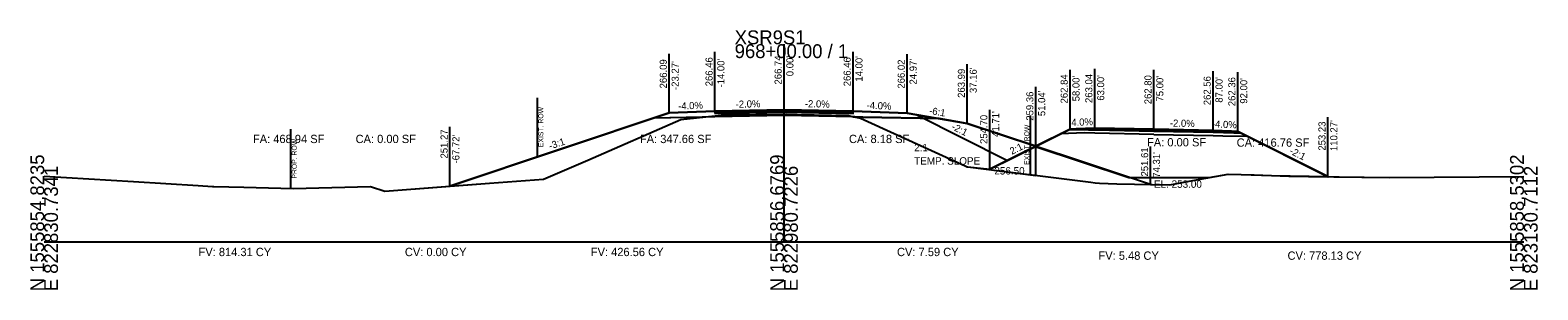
# Model space of a CAD drawing. Extents: x -26 to 823017, y -16 to 1558356.
# Drawn here: x 997.2 to 1302.8, y 7990.3 to 8042.8 of the extents above; entities that cross this region are included whole.
import ezdxf

# ---------------------------------------------------------------- set-up
doc = ezdxf.new("R2010")
doc.units = 0
for name, color, linetype in [('1', 7, 'Continuous'), ('ASPHALT_19MM1', 7, 'Continuous'), ('ASPHALT_9_5MM1', 7, 'Continuous'), ('CONST_DCH', 7, 'Continuous'), ('CONST_LV3', 7, 'Continuous'), ('Draft_XS_Grid', 7, 'Continuous'), ('DTM_CORRIDOR', 7, 'Continuous'), ('DTM_P_FINISHED_GRADE2', 7, 'Continuous'), ('DTM_X_GROUND', 7, 'Continuous'), ('SLOPE_STAKES_FILL', 7, 'Continuous'), ('X_PROFILES_1', 7, 'Continuous'), ('X_TRANS_EOP', 7, 'Continuous'), ('XS_CELL', 7, 'Continuous'), ('XS_M_SHAPES_EARTHWORK', 7, 'Continuous'), ('XS_P_DR_GRAVEL', 7, 'Continuous'), ('XS_P_GROUND', 7, 'Continuous'), ('XS_P_NULL_POINT', 7, 'Continuous'), ('XS_P_ROW', 7, 'Continuous'), ('XS_P_SHOULDER', 7, 'Continuous'), ('XS_P_SUBGRADE_GRANULAR', 7, 'Continuous'), ('XS_P_SUBGRADE_UNDERCUT', 7, 'Continuous'), ('XS_P_TX_CLEARZONE', 7, 'Continuous'), ('XS_P_TX_FS_BS', 7, 'Continuous'), ('XS_SHEET_EW_TX_AREA', 7, 'Continuous'), ('XS_SHEET_EW_TX_VOLUME', 7, 'Continuous'), ('XS_X_ROW', 7, 'Continuous')]:
    doc.layers.add(name, color=color, linetype=linetype)

msp = doc.modelspace()

# ---------------------------------------------------------------- linework, layer by layer
at = {"layer": '1'}
msp.add_lwpolyline([(1136, 8026.17), (1136, 8026.17), (1136, 8026.17), (1150, 8026.45), (1164, 8026.17), (1164, 8026.17), (1164, 8026.17), (1164, 8026.33), (1164, 8026.33), (1150, 8026.61), (1136, 8026.33), (1136, 8026.33), (1136, 8026.17)], dxfattribs=at)
at = {"layer": 'ASPHALT_19MM1'}
for points in [[(1136, 8025.96), (1136, 8025.96), (1136, 8025.96), (1150, 8026.24), (1164, 8025.96), (1164, 8025.96), (1164, 8025.96), (1164, 8026.17), (1164, 8026.17), (1150, 8026.45), (1136, 8026.17), (1136, 8026.17), (1136, 8025.96)], [(1213, 8022.67), (1225, 8022.43), (1237, 8022.19), (1237, 8022.4), (1225, 8022.64), (1213, 8022.88), (1213, 8022.67)]]:
    msp.add_lwpolyline(points, dxfattribs=at)
at = {"layer": 'ASPHALT_9_5MM1'}
msp.add_lwpolyline([(1136, 8026.33), (1136, 8026.33), (1136, 8026.33), (1150, 8026.61), (1164, 8026.33), (1164, 8026.33), (1164, 8026.33), (1164, 8026.46), (1164, 8026.46), (1150, 8026.74), (1136, 8026.46), (1136, 8026.46), (1136, 8026.33)], dxfattribs=at)
at = {"layer": 'CONST_LV3'}
for points in [[(1150, 8026.74), (1164, 8026.46)], [(1174.97, 8026.02), (1174.97, 8026.02), (1164, 8026.46)], [(1187.16, 8023.99), (1187.16, 8023.99), (1181.43, 8024.94)], [(1191.71, 8014.7), (1196.39, 8017.04), (1208, 8022.84), (1209.25, 8022.89), (1213, 8023.04)], [(1201.04, 8019.36), (1201.04, 8019.36), (1201.34, 8019.52), (1208, 8022.84), (1209.25, 8022.89), (1213, 8023.04), (1215.99, 8022.98), (1225, 8022.8), (1234.01, 8022.34), (1237, 8022.19), (1240.75, 8022.32), (1242, 8022.36), (1255.46, 8015.63), (1260.27, 8013.23), (1261.5, 8013.18), (1272.75, 8013.02), (1300, 8013.26)], [(1242, 8022.36), (1260.32, 8013.2)], [(1000, 8013.3), (1018.08, 8012.21), (1031.23, 8011.41), (1034.12, 8011.23), (1034.39, 8011.22), (1040.49, 8011.05), (1050.5, 8010.79), (1066.18, 8011.18), (1069.08, 8010.24), (1082.28, 8011.27), (1082.28, 8011.27)]]:
    msp.add_lwpolyline(points, dxfattribs=at)
at = {"layer": 'DTM_P_FINISHED_GRADE2'}
msp.add_lwpolyline([(1082.28, 8011.27), (1082.28, 8011.27), (1126.73, 8026.09), (1136, 8026.46), (1150, 8026.74), (1164, 8026.46), (1174.97, 8026.02), (1187.16, 8023.99), (1201.04, 8019.36)], dxfattribs=at)
at = {"layer": 'DTM_X_GROUND'}
for points in [[(1000, 8013.3), (1018.08, 8012.21), (1031.23, 8011.41), (1034.12, 8011.23), (1034.39, 8011.22), (1040.49, 8011.05), (1050.5, 8010.79), (1066.18, 8011.18), (1069.08, 8010.24), (1082.28, 8011.27), (1082.28, 8011.27), (1082.28, 8011.27), (1126.73, 8026.09), (1126.73, 8026.09), (1136, 8026.46), (1136, 8026.46), (1150, 8026.74), (1164, 8026.46), (1164, 8026.46), (1174.97, 8026.02), (1174.97, 8026.02), (1187.16, 8023.99), (1187.16, 8023.99), (1201.04, 8019.36), (1201.04, 8019.36), (1201.04, 8019.36), (1201.34, 8019.52), (1208, 8022.84), (1209.25, 8022.89), (1213, 8023.04), (1215.99, 8022.98), (1225, 8022.8), (1234.01, 8022.34), (1237, 8022.19), (1240.75, 8022.32), (1242, 8022.36), (1255.46, 8015.63), (1260.27, 8013.23), (1261.5, 8013.18), (1272.75, 8013.02), (1300, 8013.26)], [(1000, 8013.3), (1018.08, 8012.21), (1031.23, 8011.41), (1034.12, 8011.23), (1034.39, 8011.22), (1040.49, 8011.05), (1050.5, 8010.79), (1066.18, 8011.18), (1069.08, 8010.24), (1090.32, 8011.9), (1101.23, 8012.68), (1110.24, 8016.53), (1129.11, 8024.79), (1137.35, 8025.65), (1137.69, 8025.69), (1137.92, 8025.69), (1150.57, 8025.82), (1152.65, 8025.78), (1163.07, 8025.58), (1163.82, 8025.41), (1165.51, 8025.03), (1186.7, 8015.39), (1187.14, 8015.2), (1187.24, 8015.19), (1212.19, 8012.07), (1213.08, 8011.97), (1213.97, 8011.88), (1217.45, 8011.73), (1228.25, 8011.53), (1232.89, 8012.43), (1240.07, 8013.71), (1245.35, 8013.54), (1252.34, 8013.32), (1272.75, 8013.02), (1300, 8013.26)], [(1000, 8013.3), (1018.08, 8012.21), (1031.23, 8011.41), (1034.12, 8011.23), (1034.39, 8011.22), (1040.49, 8011.05), (1050.5, 8010.79), (1066.18, 8011.18), (1069.08, 8010.24), (1090.32, 8011.9), (1101.23, 8012.68), (1110.24, 8016.53), (1129.11, 8024.79), (1137.35, 8025.65), (1137.69, 8025.69), (1137.92, 8025.69), (1150.57, 8025.82), (1152.65, 8025.78), (1163.07, 8025.58), (1163.82, 8025.41), (1165.51, 8025.03), (1186.7, 8015.39), (1187.14, 8015.2), (1187.24, 8015.19), (1187.25, 8015.19), (1191.71, 8014.7), (1196.39, 8017.04), (1208, 8022.84), (1209.25, 8022.89), (1213, 8023.04), (1215.99, 8022.98), (1225, 8022.8), (1234.01, 8022.34), (1237, 8022.19), (1240.75, 8022.32), (1242, 8022.36), (1255.46, 8015.63), (1260.27, 8013.23), (1261.5, 8013.18), (1272.75, 8013.02), (1300, 8013.26)]]:
    msp.add_lwpolyline(points, dxfattribs=at)
at = {"layer": 'X_TRANS_EOP'}
msp.add_lwpolyline([(1213, 8022.88), (1225, 8022.64), (1237, 8022.4), (1237, 8022.56), (1225, 8022.8), (1213, 8023.04), (1213, 8022.88)], dxfattribs=at)
at = {"layer": 'XS_CELL'}
for p, q in [((1150, 8000), (1150, 8040)), ((1000, 8000), (1150, 8000)), ((1150, 8000), (1300, 8000))]:
    msp.add_line(p, q, dxfattribs=at)
at = {"layer": 'XS_M_SHAPES_EARTHWORK'}
for points in [[(1082.28, 8011.27), (1090.32, 8011.9), (1101.23, 8012.68), (1110.24, 8016.53), (1129.11, 8024.79), (1133.43, 8025.24), (1123.59, 8025.05)], [(1133.43, 8025.24), (1137.35, 8025.65), (1137.69, 8025.69), (1137.92, 8025.69), (1150.57, 8025.82), (1152.65, 8025.78), (1163.07, 8025.58), (1163.82, 8025.41), (1164.38, 8025.29), (1164, 8025.29), (1150, 8025.57), (1136, 8025.29), (1134, 8025.25)], [(1164.38, 8025.29), (1165.51, 8025.03), (1186.7, 8015.39), (1187.14, 8015.2), (1187.24, 8015.19), (1201.04, 8013.46), (1201.04, 8019.36), (1187.16, 8023.99), (1181.43, 8024.94), (1166, 8025.25)]]:
    msp.add_lwpolyline(points, close=True, dxfattribs=at)
at = {"layer": 'XS_P_DR_GRAVEL'}
for points in [[(1209.25, 8022.89), (1208, 8022.84), (1207.89, 8022.79), (1207.86, 8022.77), (1211.72, 8022.69), (1213, 8022.67), (1213, 8022.76), (1213, 8023.04), (1209.25, 8022.89)], [(1240.75, 8022.41), (1237, 8022.56), (1237, 8022.28), (1237, 8022.19), (1241.18, 8022.1), (1242.57, 8022.08), (1242.43, 8022.15), (1242, 8022.36), (1240.75, 8022.41)]]:
    msp.add_lwpolyline(points, dxfattribs=at)
at = {"layer": 'XS_P_GROUND'}
msp.add_line((1176.92, 8025.7), (1195.31, 8016.5), dxfattribs=at)
for points in [[(1126.73, 8026.09), (1082.28, 8011.27)], [(1174.97, 8026.02), (1187.16, 8023.99), (1201.04, 8019.36)], [(1224.31, 8011.61), (1224.31, 8011.61), (1187.16, 8023.99), (1187.16, 8023.99), (1174.97, 8026.02)], [(1208, 8022.84), (1191.71, 8014.7)], [(1242, 8022.36), (1260.27, 8013.23)], [(1224.31, 8011.61), (1228.25, 8011.53), (1228.25, 8011.53), (1232.89, 8012.43), (1232.89, 8012.43), (1240.07, 8013.71), (1240.07, 8013.71), (1245.35, 8013.54), (1245.35, 8013.54), (1252.34, 8013.32), (1252.34, 8013.32), (1260.32, 8013.2), (1260.32, 8013.2)], [(1224.31, 8011.61), (1228.25, 8011.53), (1228.25, 8011.53), (1232.89, 8012.43), (1232.89, 8012.43), (1240.07, 8013.71), (1240.07, 8013.71), (1245.35, 8013.54), (1245.35, 8013.54), (1252.34, 8013.32), (1252.34, 8013.32), (1260.32, 8013.2), (1260.32, 8013.2)]]:
    msp.add_lwpolyline(points, dxfattribs=at)
at = {"layer": 'XS_P_ROW'}
msp.add_line((1050, 8010.81), (1050, 8022.81), dxfattribs=at)
at = {"layer": 'XS_P_SHOULDER'}
for points in [[(1136, 8026.46), (1126.73, 8026.09)], [(1164, 8026.46), (1174.97, 8026.02)], [(1208, 8022.84), (1209.25, 8022.89), (1213, 8023.04)], [(1242, 8022.36), (1240.75, 8022.41), (1237, 8022.56)]]:
    msp.add_lwpolyline(points, dxfattribs=at)
at = {"layer": 'XS_P_SUBGRADE_GRANULAR'}
for points in [[(1136, 8025.29), (1134, 8025.25), (1123.59, 8025.05)], [(1150, 8025.57), (1136, 8025.29)], [(1164, 8025.29), (1164, 8025.29), (1150, 8025.57)], [(1164, 8025.29), (1166, 8025.25), (1181.43, 8024.94)], [(1213, 8022), (1211, 8022.04), (1206, 8021.84)], [(1225, 8021.76), (1213, 8022)], [(1225, 8021.76), (1237, 8021.52)], [(1237, 8021.52), (1239, 8021.48), (1243.96, 8021.38)]]:
    msp.add_lwpolyline(points, dxfattribs=at)
at = {"layer": 'XS_P_SUBGRADE_UNDERCUT'}
msp.add_lwpolyline([(1219.91, 8013), (1225.81, 8013), (1236.17, 8013), (1240.07, 8013.71), (1242.71, 8013.63), (1248.85, 8013.43), (1260.27, 8013.23), (1242, 8022.36), (1237, 8022.56), (1234.01, 8022.62), (1225, 8022.8), (1215.99, 8022.98), (1213, 8023.04), (1209.25, 8022.89), (1208, 8022.84), (1200.95, 8019.32)], close=True, dxfattribs=at)
at = {"layer": 'XS_P_TX_CLEARZONE'}
for p, q in [((1126.73, 8026.09), (1126.73, 8038.09)), ((1136, 8026.46), (1136, 8038.46)), ((1150, 8026.74), (1150, 8038.74)), ((1164, 8026.46), (1164, 8038.46)), ((1174.97, 8026.02), (1174.97, 8038.02)), ((1187.16, 8023.99), (1187.16, 8035.99)), ((1187.16, 8023.99), (1187.16, 8035.99)), ((1208, 8022.84), (1208, 8034.84)), ((1213, 8023.04), (1213, 8035.04)), ((1225, 8022.8), (1225, 8034.8)), ((1237, 8022.56), (1237, 8034.56)), ((1242, 8022.36), (1242, 8034.36)), ((1201.04, 8019.36), (1201.04, 8031.36)), ((1191.71, 8014.7), (1191.71, 8026.7)), ((1260.27, 8013.23), (1260.27, 8025.23)), ((1082.28, 8011.27), (1082.28, 8023.27)), ((1224.31, 8011.61), (1224.31, 8019.3))]:
    msp.add_line(p, q, dxfattribs=at)
at = {"layer": 'XS_X_ROW'}
for p, q in [((1100, 8017.18), (1100, 8029.18)), ((1200, 8013.59), (1200, 8025.59))]:
    msp.add_line(p, q, dxfattribs=at)

# ---------------------------------------------------------------- texts
at = {"layer": 'CONST_DCH'}
for p in [(1135.92, 8026.34), (1149.92, 8026.62), (1163.92, 8026.34)]:
    msp.add_text('X', height=0.24, dxfattribs=at).set_placement(p)
at = {"layer": 'CONST_LV3'}
for p in [(1174.89, 8025.9), (1187.09, 8023.87), (1200.96, 8019.24), (1260.25, 8013.08), (1082.2, 8011.15), (1224.23, 8011.49)]:
    msp.add_text('X', height=0.24, dxfattribs=at).set_placement(p)
at = {"layer": 'Draft_XS_Grid'}
msp.add_text('-', height=0.0001, dxfattribs=at).set_placement((1000, 8000))
at = {"layer": 'DTM_CORRIDOR'}
for p in [(1212.92, 8022.92), (1224.92, 8022.68), (1236.92, 8022.44)]:
    msp.add_text('X', height=0.24, dxfattribs=at).set_placement(p)
at = {"layer": 'SLOPE_STAKES_FILL'}
for p in [(1191.63, 8014.58), (1260.19, 8013.11)]:
    msp.add_text('X', height=0.24, dxfattribs=at).set_placement(p)
at = {"layer": 'X_PROFILES_1'}
msp.add_text('X', height=0.24, dxfattribs=at).set_placement((1260.25, 8013.08))
at = {"layer": 'XS_CELL'}
for s, p in [('XSR9S1', (1140, 8040)), ('968+00.00 / 1', (1140, 8037.2))]:
    msp.add_text(s, height=2.8, dxfattribs=at).set_placement(p)
for s, p in [('N 1555854.8235', (1000, 7990)), ('E 822830.7341', (1002.8, 7990)), ('N 1555856.6769', (1150, 7990)), ('E 822980.7226', (1152.8, 7990)), ('N 1555858.5302', (1300, 7990)), ('E 823130.7112', (1302.8, 7990))]:
    msp.add_text(s, height=2.8, rotation=90, dxfattribs=at).set_placement(p)
at = {"layer": 'XS_P_GROUND'}
for s, p in [('2:1', (1176.4, 8018.34)), ('TEMP. SLOPE', (1176.4, 8015.64)), ('256.50', (1192.65, 8013.64))]:
    msp.add_text(s, height=1.5, dxfattribs=at).set_placement(p)
at = {"layer": 'XS_P_NULL_POINT'}
for p in [(1200.96, 8019.24), (1191.63, 8014.58), (1260.19, 8013.11), (1082.2, 8011.15)]:
    msp.add_text('X', height=0.24, dxfattribs=at).set_placement(p)
at = {"layer": 'XS_P_ROW'}
msp.add_text('PROP. ROW', height=1, rotation=90, dxfattribs=at).set_placement((1051.2, 8012.81))
at = {"layer": 'XS_P_SHOULDER'}
for p in [(1126.65, 8025.97), (1174.89, 8025.9), (1207.92, 8022.72), (1241.92, 8022.24)]:
    msp.add_text('X', height=0.24, dxfattribs=at).set_placement(p)
at = {"layer": 'XS_P_SUBGRADE_GRANULAR'}
msp.add_text('X', height=0.24, dxfattribs=at).set_placement((1187.09, 8023.87))
at = {"layer": 'XS_P_SUBGRADE_UNDERCUT'}
msp.add_text('EL. 253.00', height=1.5, dxfattribs=at).set_placement((1225.02, 8010.95))
at = {"layer": 'XS_P_TX_CLEARZONE'}
for s, p in [('266.09', (1126.25, 8031.07)), ("-23.27'", (1128.65, 8030.75)), ('266.46', (1135.52, 8031.49)), ("-14.00'", (1137.92, 8031.25)), ('266.74', (1149.52, 8031.85)), ("0.00'", (1151.92, 8033.53)), ('266.46', (1163.52, 8031.49)), ("14.00'", (1165.92, 8032.43)), ('266.02', (1174.49, 8031.02)), ("24.97'", (1176.89, 8031.86)), ('263.99', (1186.68, 8029.15)), ("37.16'", (1189.08, 8030.12)), ('262.84', (1207.52, 8028.02)), ("58.00'", (1209.92, 8028.45)), ('263.04', (1212.52, 8028.11)), ("63.00'", (1214.92, 8028.58)), ('262.80', (1224.52, 8027.86)), ("75.00'", (1226.92, 8028.41)), ('262.56', (1236.52, 8027.66)), ('259.36', (1200.56, 8024.53)), ("51.04'", (1202.96, 8025.45)), ("87.00'", (1238.92, 8028.17)), ('262.36', (1241.52, 8027.46)), ("92.00'", (1243.92, 8027.97)), ('254.70', (1191.23, 8019.82)), ("41.71'", (1193.63, 8021.26)), ('253.23', (1259.79, 8018.47)), ("110.27'", (1262.19, 8018.38)), ('251.27', (1081.8, 8016.88)), ("-67.72'", (1084.2, 8015.86)), ('251.61', (1223.83, 8013.24)), ("74.31'", (1226.23, 8012.99))]:
    msp.add_text(s, height=1.44, rotation=90, dxfattribs=at).set_placement(p)
at = {"layer": 'XS_P_TX_FS_BS'}
for s, rotation, p in [('-4.0%', 2.2906, (1128.55, 8026.76)), ('-2.0%', 1.1458, (1140.2, 8027.14)), ('-2.0%', 358.8542, (1154.22, 8027.26)), ('-4.0%', 357.7094, (1166.72, 8026.95)), ('-6:1', 350.5358, (1179.34, 8025.9)), ('4.0%', 2.2906, (1208.27, 8023.45)), ('-2.0%', 358.8542, (1228.22, 8023.34)), ('-4.0%', 357.7094, (1236.73, 8023.17)), ('-2:1', 333.4349, (1183.82, 8022.86)), ('-3:1', 18.4332, (1102.59, 8018.68)), ('2:1', 26.5651, (1196.21, 8017.6)), ('-2:1', 333.4349, (1252.35, 8017.95))]:
    msp.add_text(s, height=1.44, rotation=rotation, dxfattribs=at).set_placement(p)
at = {"layer": 'XS_SHEET_EW_TX_AREA'}
for s, p in [('FA: 468.94 SF', (1042.33, 8020)), ('CA: 0.00 SF', (1063.14, 8020)), ('FA: 347.66 SF', (1120.79, 8020)), ('CA: 8.18 SF', (1163.17, 8020)), ('FA: 0.00 SF', (1223.6, 8019.33)), ('CA: 416.76 SF', (1241.78, 8019.26))]:
    msp.add_text(s, height=1.68, dxfattribs=at).set_placement(p)
at = {"layer": 'XS_SHEET_EW_TX_VOLUME'}
for s, p in [('FV: 814.31 CY', (1031.3, 7997.12)), ('CV: 0.00 CY', (1073.13, 7997.12)), ('FV: 426.56 CY', (1110.83, 7997.12)), ('CV: 7.59 CY', (1172.91, 7997.12)), ('FV: 5.48 CY', (1213.76, 7996.38)), ('CV: 778.13 CY', (1252.09, 7996.38))]:
    msp.add_text(s, height=1.68, dxfattribs=at).set_placement(p)
at = {"layer": 'XS_X_ROW'}
for p in [(1101.2, 8019.18), (1199.73, 8015.59)]:
    msp.add_text('EXIST. ROW', height=1, rotation=90, dxfattribs=at).set_placement(p)

doc.saveas('drawing.dxf')
